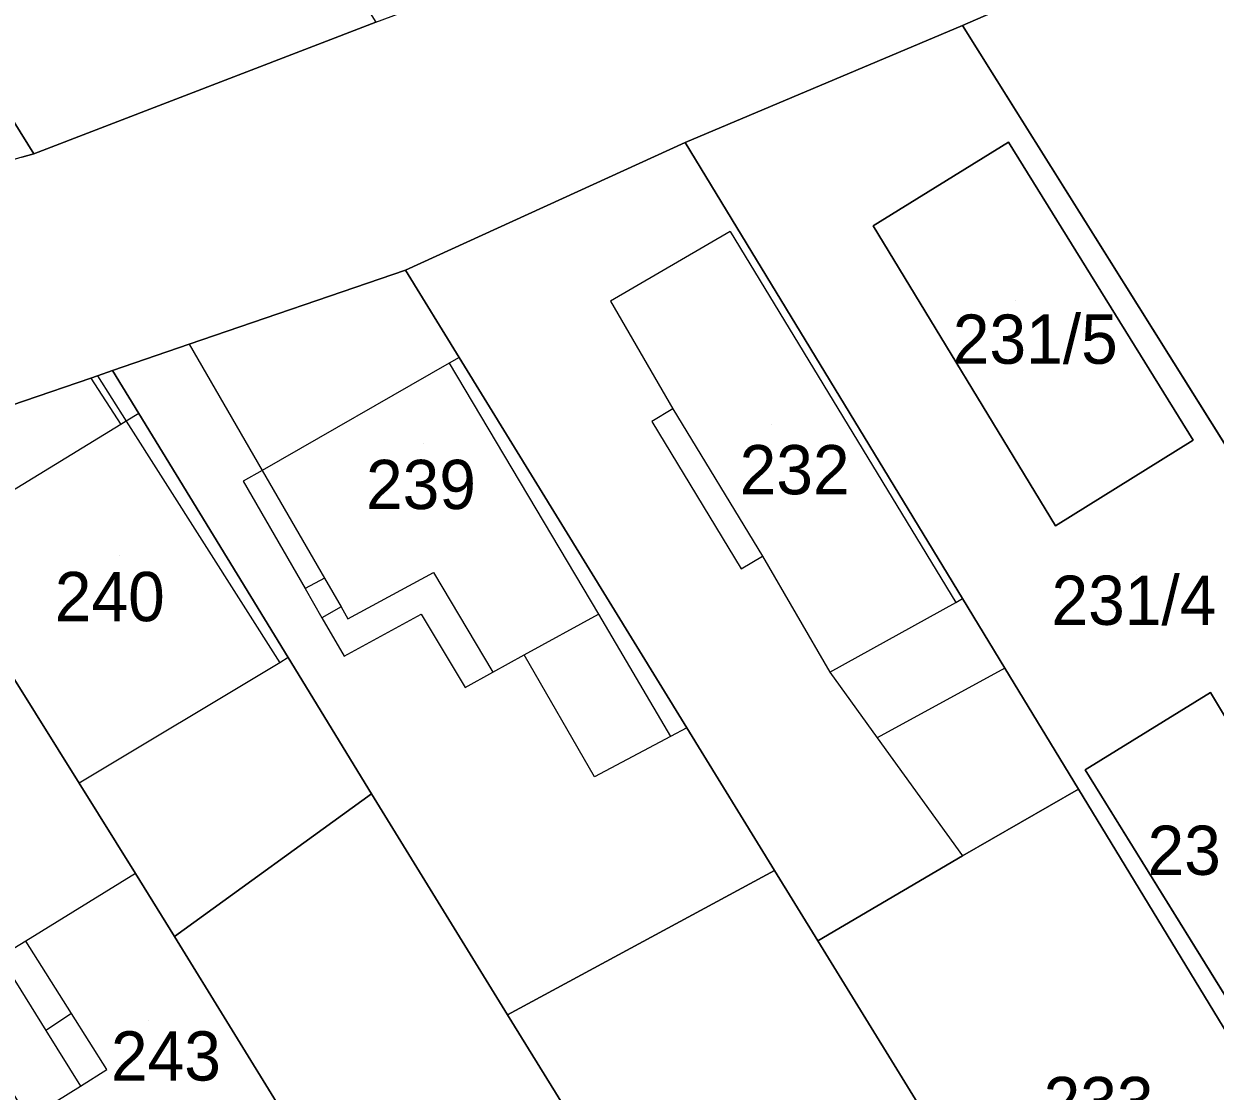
# Model space of a CAD drawing. Extents: x -263943 to -261149, y -1236934 to -1230686.
# Drawn here: x -262444.57 to -262396.23, y -1235556.72 to -1235513.39 of the extents above; entities that cross this region are included whole.
import ezdxf

# ---------------------------------------------------------------- set-up
doc = ezdxf.new("R2010")
doc.units = 0
for name, color, linetype in [('body_kn', 7, 'Continuous'), ('kladpar_druhypozemkov', 7, 'Continuous'), ('kladpar_hranice', 7, 'Continuous'), ('kladpar_parcelnecisla', 7, 'Continuous'), ('kladpar_plochy', 7, 'Continuous'), ('zappar_hrandruhpozemk', 7, 'Continuous')]:
    doc.layers.add(name, color=color, linetype=linetype)

msp = doc.modelspace()

# ---------------------------------------------------------------- linework, layer by layer
at = {"layer": 'body_kn'}
for p, q in [((-262406.48, -1235513.46), (-262406.48, -1235513.46)), ((-262417.74, -1235518.21), (-262417.74, -1235518.21)), ((-262404.61, -1235518.2), (-262404.61, -1235518.2)), ((-262404.61, -1235518.2), (-262404.61, -1235518.2)), ((-262444.17, -1235518.67), (-262444.17, -1235518.67)), ((-262415.91, -1235521.82), (-262415.91, -1235521.82)), ((-262415.64, -1235521.66), (-262415.64, -1235521.66)), ((-262410.11, -1235521.59), (-262410.11, -1235521.59)), ((-262429.08, -1235523.39), (-262429.08, -1235523.39)), ((-262420.77, -1235524.65), (-262420.77, -1235524.65)), ((-262437.86, -1235526.4), (-262437.86, -1235526.4)), ((-262437.86, -1235526.4), (-262437.86, -1235526.4)), ((-262427.31, -1235527.16), (-262427.31, -1235527.16)), ((-262426.91, -1235526.93), (-262426.91, -1235526.93)), ((-262426.91, -1235526.93), (-262426.91, -1235526.93)), ((-262441.86, -1235527.77), (-262441.86, -1235527.77)), ((-262441.86, -1235527.77), (-262441.86, -1235527.77)), ((-262441.59, -1235527.68), (-262441.59, -1235527.68)), ((-262441.59, -1235527.68), (-262441.59, -1235527.68)), ((-262440.98, -1235527.47), (-262440.98, -1235527.47)), ((-262439.91, -1235529.21), (-262439.91, -1235529.21)), ((-262439.91, -1235529.21), (-262439.91, -1235529.21)), ((-262418.23, -1235529.02), (-262418.23, -1235529.02)), ((-262418.23, -1235529.02), (-262418.23, -1235529.02)), ((-262440.64, -1235529.65), (-262440.64, -1235529.65)), ((-262440.42, -1235529.52), (-262440.42, -1235529.52)), ((-262419.09, -1235529.54), (-262419.09, -1235529.54)), ((-262397.12, -1235530.29), (-262397.12, -1235530.29)), ((-262434.9, -1235531.52), (-262434.9, -1235531.52)), ((-262435.67, -1235531.96), (-262435.67, -1235531.96)), ((-262402.71, -1235533.77), (-262402.71, -1235533.77)), ((-262414.6, -1235535), (-262414.6, -1235535)), ((-262415.46, -1235535.52), (-262415.46, -1235535.52)), ((-262432.37, -1235535.9), (-262432.37, -1235535.9)), ((-262432.37, -1235535.9), (-262432.37, -1235535.9)), ((-262427.95, -1235535.67), (-262427.95, -1235535.67)), ((-262433.16, -1235536.32), (-262433.16, -1235536.32)), ((-262406.75, -1235536.88), (-262406.75, -1235536.88)), ((-262406.75, -1235536.88), (-262406.75, -1235536.88)), ((-262406.48, -1235536.72), (-262406.48, -1235536.72)), ((-262431.7, -1235537.06), (-262431.7, -1235537.06)), ((-262428.45, -1235537.36), (-262428.45, -1235537.36)), ((-262421.25, -1235537.35), (-262421.25, -1235537.35)), ((-262432.48, -1235537.5), (-262432.48, -1235537.5)), ((-262431.42, -1235537.54), (-262431.42, -1235537.54)), ((-262434.19, -1235539.33), (-262434.19, -1235539.33)), ((-262434.19, -1235539.33), (-262434.19, -1235539.33)), ((-262433.85, -1235539.12), (-262433.85, -1235539.12)), ((-262433.85, -1235539.12), (-262433.85, -1235539.12)), ((-262431.58, -1235539.06), (-262431.58, -1235539.06)), ((-262424.27, -1235539.01), (-262424.27, -1235539.01)), ((-262424.27, -1235539.01), (-262424.27, -1235539.01)), ((-262425.54, -1235539.71), (-262425.54, -1235539.71)), ((-262411.86, -1235539.71), (-262411.86, -1235539.71)), ((-262404.76, -1235539.55), (-262404.76, -1235539.55)), ((-262404.76, -1235539.55), (-262404.76, -1235539.55)), ((-262426.67, -1235540.33), (-262426.67, -1235540.33)), ((-262396.42, -1235540.54), (-262396.42, -1235540.54)), ((-262396.42, -1235540.54), (-262396.42, -1235540.54)), ((-262417.67, -1235541.97), (-262417.67, -1235541.97)), ((-262417.67, -1235541.97), (-262417.67, -1235541.97)), ((-262418.33, -1235542.32), (-262418.33, -1235542.32)), ((-262409.94, -1235542.37), (-262409.94, -1235542.37)), ((-262401.5, -1235543.68), (-262401.5, -1235543.68)), ((-262401.5, -1235543.68), (-262401.5, -1235543.68)), ((-262442.33, -1235544.22), (-262442.33, -1235544.22)), ((-262421.41, -1235543.96), (-262421.41, -1235543.96)), ((-262430.47, -1235544.65), (-262430.47, -1235544.65)), ((-262430.47, -1235544.65), (-262430.47, -1235544.65)), ((-262401.77, -1235544.46), (-262401.77, -1235544.46)), ((-262401.77, -1235544.46), (-262401.77, -1235544.46)), ((-262406.48, -1235547.17), (-262406.48, -1235547.17)), ((-262440.04, -1235547.88), (-262440.04, -1235547.88)), ((-262440.04, -1235547.88), (-262440.04, -1235547.88)), ((-262414.11, -1235547.76), (-262414.11, -1235547.76)), ((-262438.46, -1235550.44), (-262438.46, -1235550.44)), ((-262444.5, -1235550.63), (-262444.5, -1235550.63)), ((-262444.5, -1235550.63), (-262444.5, -1235550.63)), ((-262412.35, -1235550.62), (-262412.35, -1235550.62)), ((-262442.64, -1235553.57), (-262442.64, -1235553.57)), ((-262424.94, -1235553.62), (-262424.94, -1235553.62)), ((-262424.94, -1235553.62), (-262424.94, -1235553.62)), ((-262443.68, -1235554.25), (-262443.68, -1235554.25)), ((-262441.2, -1235555.84), (-262441.2, -1235555.84)), ((-262442.27, -1235556.51), (-262442.27, -1235556.51))]:
    msp.add_line(p, q, dxfattribs=at)
at = {"layer": 'kladpar_druhypozemkov'}
for p, q in [((-262404.35, -1235524.64), (-262404.35, -1235524.64)), ((-262414.25, -1235529.64), (-262414.25, -1235529.64)), ((-262428.35, -1235530.44), (-262428.35, -1235530.44)), ((-262440.7, -1235534.99), (-262440.7, -1235534.99)), ((-262399.4, -1235535.74), (-262399.4, -1235535.74)), ((-262439.5, -1235553.84), (-262439.5, -1235553.84)), ((-262401.25, -1235556.04), (-262401.25, -1235556.04))]:
    msp.add_line(p, q, dxfattribs=at)
at = {"layer": 'kladpar_hranice'}
msp.add_line((-262396.42, -1235540.54), (-262401.5, -1235543.68), dxfattribs=at)
for points in [[(-262462.76, -1235488.73), (-262466.03, -1235483.85), (-262462.31, -1235481.58), (-262465.71, -1235475.96), (-262469.51, -1235478.23), (-262474.18, -1235470.34), (-262497.22, -1235433.33), (-262503.23, -1235423.24), (-262504.55, -1235421.03), (-262504.18, -1235420.81), (-262495.83, -1235415.83), (-262492.83, -1235420.04), (-262489.45, -1235425.16), (-262475.39, -1235445.94), (-262473.48, -1235444.88), (-262430.29, -1235513.32), (-262444.17, -1235518.67), (-262462.76, -1235488.73)], [(-262451.3, -1235520.8), (-262455.26, -1235521.99), (-262458.39, -1235516.94), (-262464.13, -1235507.7), (-262466.56, -1235503.77), (-262481.31, -1235480), (-262483.69, -1235476.16), (-262483.32, -1235475.94), (-262475.61, -1235471.22), (-262474.18, -1235470.34), (-262469.51, -1235478.23), (-262466.03, -1235483.85), (-262462.76, -1235488.73), (-262444.17, -1235518.67), (-262444.65, -1235518.81), (-262450.59, -1235520.59), (-262451.3, -1235520.8)], [(-262444.65, -1235518.81), (-262444.17, -1235518.67), (-262430.29, -1235513.32), (-262423.68, -1235510.86), (-262421.22, -1235509.96), (-262420.29, -1235509.62), (-262414, -1235507.3), (-262408.2, -1235505.17), (-262402.61, -1235503.12), (-262384.68, -1235495.02)], [(-262395.05, -1235510.73), (-262402, -1235511.5), (-262406.48, -1235513.46), (-262417.74, -1235518.21), (-262429.08, -1235523.39), (-262437.86, -1235526.4), (-262440.98, -1235527.47), (-262441.59, -1235527.68), (-262441.86, -1235527.77), (-262449.95, -1235530.54)], [(-262384.97, -1235547.8), (-262406.48, -1235513.46), (-262402, -1235511.5), (-262395.05, -1235510.73), (-262378.05, -1235537.97), (-262363.48, -1235561.29), (-262363.25, -1235561.66), (-262372.64, -1235567.43), (-262384.97, -1235547.8)], [(-262401.5, -1235543.68), (-262395.09, -1235554.03), (-262395.72, -1235554.42), (-262401.77, -1235544.46), (-262404.76, -1235539.55), (-262406.48, -1235536.72), (-262415.64, -1235521.66), (-262417.74, -1235518.21), (-262406.48, -1235513.46), (-262384.97, -1235547.8), (-262390.14, -1235550.98), (-262396.42, -1235540.54)], [(-262401.77, -1235544.46), (-262406.48, -1235547.17), (-262412.35, -1235550.62), (-262414.11, -1235547.76), (-262417.67, -1235541.97), (-262426.91, -1235526.93), (-262429.08, -1235523.39), (-262417.74, -1235518.21), (-262415.64, -1235521.66), (-262406.48, -1235536.72), (-262404.76, -1235539.55), (-262401.77, -1235544.46)], [(-262402.71, -1235533.77), (-262397.12, -1235530.29), (-262404.61, -1235518.2), (-262410.11, -1235521.59), (-262402.71, -1235533.77)], [(-262404.61, -1235518.2), (-262397.12, -1235530.29), (-262402.71, -1235533.77), (-262410.11, -1235521.59), (-262404.61, -1235518.2)], [(-262430.47, -1235544.65), (-262433.85, -1235539.12), (-262439.91, -1235529.21), (-262440.98, -1235527.47), (-262437.86, -1235526.4), (-262429.08, -1235523.39), (-262426.91, -1235526.93), (-262417.67, -1235541.97), (-262414.11, -1235547.76), (-262424.94, -1235553.62), (-262430.47, -1235544.65)], [(-262440.04, -1235547.88), (-262442.33, -1235544.22), (-262448.45, -1235534.43), (-262450.38, -1235530.69), (-262449.95, -1235530.54), (-262441.86, -1235527.77), (-262441.59, -1235527.68), (-262440.98, -1235527.47), (-262439.91, -1235529.21), (-262433.85, -1235539.12), (-262430.47, -1235544.65), (-262438.46, -1235550.44), (-262440.04, -1235547.88)], [(-262441.61, -1235562.36), (-262444.38, -1235557.83), (-262448.9, -1235550.42), (-262452.44, -1235544.63), (-262458.31, -1235535.02), (-262459.13, -1235533.68), (-262450.38, -1235530.69), (-262448.45, -1235534.43), (-262442.33, -1235544.22), (-262440.04, -1235547.88), (-262438.46, -1235550.44), (-262434, -1235557.69), (-262441.61, -1235562.36)], [(-262396.42, -1235540.54), (-262390.14, -1235550.98), (-262395.09, -1235554.03), (-262401.5, -1235543.68), (-262396.42, -1235540.54)], [(-262434, -1235557.69), (-262438.46, -1235550.44), (-262430.47, -1235544.65), (-262424.94, -1235553.62), (-262407.69, -1235581.56), (-262416.07, -1235586.4), (-262434, -1235557.69)], [(-262395.72, -1235554.42), (-262386.28, -1235569.73), (-262396.68, -1235576.1), (-262412.35, -1235550.62), (-262406.48, -1235547.17), (-262401.77, -1235544.46), (-262395.72, -1235554.42)], [(-262424.94, -1235553.62), (-262414.11, -1235547.76), (-262412.35, -1235550.62), (-262396.68, -1235576.1), (-262407.34, -1235582.13), (-262407.69, -1235581.56), (-262424.94, -1235553.62)]]:
    msp.add_lwpolyline(points, dxfattribs=at)
at = {"layer": 'kladpar_plochy'}
for p, q in [((-262444.17, -1235518.67), (-262462.76, -1235488.73)), ((-262430.29, -1235513.32), (-262444.17, -1235518.67)), ((-262417.74, -1235518.21), (-262406.48, -1235513.46)), ((-262406.48, -1235513.46), (-262384.97, -1235547.8)), ((-262415.64, -1235521.66), (-262417.74, -1235518.21)), ((-262404.61, -1235518.2), (-262410.11, -1235521.59)), ((-262397.12, -1235530.29), (-262404.61, -1235518.2)), ((-262406.48, -1235536.72), (-262415.64, -1235521.66)), ((-262410.11, -1235521.59), (-262402.71, -1235533.77)), ((-262402.71, -1235533.77), (-262397.12, -1235530.29)), ((-262404.76, -1235539.55), (-262406.48, -1235536.72)), ((-262401.77, -1235544.46), (-262404.76, -1235539.55)), ((-262396.42, -1235540.54), (-262401.5, -1235543.68)), ((-262390.14, -1235550.98), (-262396.42, -1235540.54)), ((-262401.5, -1235543.68), (-262395.09, -1235554.03)), ((-262395.72, -1235554.42), (-262401.77, -1235544.46))]:
    msp.add_line(p, q, dxfattribs=at)
for points in [[(-262451.3, -1235520.8), (-262455.26, -1235521.99), (-262458.39, -1235516.94), (-262464.13, -1235507.7), (-262466.56, -1235503.77), (-262481.31, -1235480), (-262483.69, -1235476.16), (-262483.32, -1235475.94), (-262475.61, -1235471.22), (-262474.18, -1235470.34), (-262469.51, -1235478.23), (-262466.03, -1235483.85), (-262462.76, -1235488.73), (-262444.17, -1235518.67), (-262444.65, -1235518.81), (-262450.59, -1235520.59)], [(-262384.97, -1235547.8), (-262406.48, -1235513.46), (-262402, -1235511.5), (-262395.05, -1235510.73), (-262378.05, -1235537.97), (-262363.48, -1235561.29), (-262363.25, -1235561.66), (-262372.64, -1235567.43)], [(-262401.77, -1235544.46), (-262406.48, -1235547.17), (-262412.35, -1235550.62), (-262414.11, -1235547.76), (-262417.67, -1235541.97), (-262426.91, -1235526.93), (-262429.08, -1235523.39), (-262417.74, -1235518.21), (-262415.64, -1235521.66), (-262406.48, -1235536.72), (-262404.76, -1235539.55)], [(-262404.61, -1235518.2), (-262397.12, -1235530.29), (-262402.71, -1235533.77), (-262410.11, -1235521.59)], [(-262430.47, -1235544.65), (-262433.85, -1235539.12), (-262439.91, -1235529.21), (-262440.98, -1235527.47), (-262437.86, -1235526.4), (-262429.08, -1235523.39), (-262426.91, -1235526.93), (-262417.67, -1235541.97), (-262414.11, -1235547.76), (-262424.94, -1235553.62)], [(-262440.04, -1235547.88), (-262442.33, -1235544.22), (-262448.45, -1235534.43), (-262450.38, -1235530.69), (-262449.95, -1235530.54), (-262441.86, -1235527.77), (-262441.59, -1235527.68), (-262440.98, -1235527.47), (-262439.91, -1235529.21), (-262433.85, -1235539.12), (-262430.47, -1235544.65), (-262438.46, -1235550.44)], [(-262441.61, -1235562.36), (-262444.38, -1235557.83), (-262448.9, -1235550.42), (-262452.44, -1235544.63), (-262458.31, -1235535.02), (-262459.13, -1235533.68), (-262450.38, -1235530.69), (-262448.45, -1235534.43), (-262442.33, -1235544.22), (-262440.04, -1235547.88), (-262438.46, -1235550.44), (-262434, -1235557.69)], [(-262396.42, -1235540.54), (-262390.14, -1235550.98), (-262395.09, -1235554.03), (-262401.5, -1235543.68)], [(-262434, -1235557.69), (-262438.46, -1235550.44), (-262430.47, -1235544.65), (-262424.94, -1235553.62), (-262407.69, -1235581.56), (-262416.07, -1235586.4)], [(-262395.72, -1235554.42), (-262386.28, -1235569.73), (-262396.68, -1235576.1), (-262412.35, -1235550.62), (-262406.48, -1235547.17), (-262401.77, -1235544.46)], [(-262424.94, -1235553.62), (-262414.11, -1235547.76), (-262412.35, -1235550.62), (-262396.68, -1235576.1), (-262407.34, -1235582.13), (-262407.69, -1235581.56)]]:
    msp.add_lwpolyline(points, close=True, dxfattribs=at)
for points in [[(-262444.65, -1235518.81), (-262444.17, -1235518.67), (-262430.29, -1235513.32), (-262423.68, -1235510.86), (-262421.22, -1235509.96), (-262420.29, -1235509.62), (-262414, -1235507.3), (-262408.2, -1235505.17), (-262402.61, -1235503.12), (-262384.68, -1235495.02)], [(-262395.05, -1235510.73), (-262402, -1235511.5), (-262406.48, -1235513.46), (-262417.74, -1235518.21), (-262429.08, -1235523.39), (-262437.86, -1235526.4), (-262440.98, -1235527.47), (-262441.59, -1235527.68), (-262441.86, -1235527.77), (-262449.95, -1235530.54)]]:
    msp.add_lwpolyline(points, dxfattribs=at)
at = {"layer": 'zappar_hrandruhpozemk'}
for p, q in [((-262415.91, -1235521.82), (-262406.75, -1235536.88)), ((-262437.86, -1235526.4), (-262434.9, -1235531.52)), ((-262427.31, -1235527.16), (-262434.9, -1235531.52)), ((-262426.91, -1235526.93), (-262427.31, -1235527.16)), ((-262441.86, -1235527.77), (-262440.64, -1235529.65)), ((-262418.23, -1235529.02), (-262414.6, -1235535)), ((-262419.09, -1235529.54), (-262415.46, -1235535.52)), ((-262432.37, -1235535.9), (-262433.16, -1235536.32)), ((-262411.86, -1235539.71), (-262406.75, -1235536.88)), ((-262406.75, -1235536.88), (-262406.48, -1235536.72)), ((-262431.7, -1235537.06), (-262432.48, -1235537.5)), ((-262424.27, -1235539.01), (-262421.25, -1235537.35)), ((-262434.19, -1235539.33), (-262442.33, -1235544.22)), ((-262433.85, -1235539.12), (-262434.19, -1235539.33)), ((-262421.41, -1235543.96), (-262424.27, -1235539.01)), ((-262404.76, -1235539.55), (-262409.94, -1235542.37)), ((-262440.04, -1235547.88), (-262444.5, -1235550.63)), ((-262442.64, -1235553.57), (-262444.5, -1235550.63)), ((-262442.64, -1235553.57), (-262443.68, -1235554.25)), ((-262441.2, -1235555.84), (-262442.64, -1235553.57))]:
    msp.add_line(p, q, dxfattribs=at)
for points in [[(-262415.91, -1235521.82), (-262420.77, -1235524.65), (-262418.23, -1235529.02), (-262419.09, -1235529.54)], [(-262427.31, -1235527.16), (-262421.25, -1235537.35), (-262418.33, -1235542.32)], [(-262441.59, -1235527.68), (-262440.42, -1235529.52), (-262434.19, -1235539.33)], [(-262439.91, -1235529.21), (-262440.42, -1235529.52), (-262440.64, -1235529.65), (-262448.19, -1235534.27), (-262448.45, -1235534.43)], [(-262434.9, -1235531.52), (-262435.67, -1235531.96), (-262433.16, -1235536.32), (-262432.48, -1235537.5), (-262431.58, -1235539.06), (-262428.45, -1235537.36), (-262426.67, -1235540.33), (-262425.54, -1235539.71), (-262424.27, -1235539.01)], [(-262434.9, -1235531.52), (-262432.37, -1235535.9), (-262431.7, -1235537.06)], [(-262415.46, -1235535.52), (-262414.6, -1235535), (-262411.86, -1235539.71)], [(-262431.7, -1235537.06), (-262431.42, -1235537.54), (-262427.95, -1235535.67), (-262425.54, -1235539.71)], [(-262411.86, -1235539.71), (-262409.94, -1235542.37), (-262406.48, -1235547.17)], [(-262417.67, -1235541.97), (-262418.33, -1235542.32), (-262421.41, -1235543.96)], [(-262444.5, -1235550.63), (-262445.53, -1235551.27), (-262443.68, -1235554.25), (-262442.27, -1235556.51)], [(-262444.38, -1235557.83), (-262442.27, -1235556.51), (-262441.2, -1235555.84)]]:
    msp.add_lwpolyline(points, dxfattribs=at)

# ---------------------------------------------------------------- texts
at = {"layer": 'kladpar_parcelnecisla'}
for s, p in [('231/5', (-262406.874, -1235527.19)), ('232', (-262415.525, -1235532.49)), ('239', (-262430.688, -1235533.09)), ('240', (-262443.317, -1235537.64)), ('231/4', (-262402.869, -1235537.79)), ('231/3', (-262398.971, -1235547.94)), ('243', (-262441.038, -1235556.29)), ('233', (-262403.19, -1235558.14))]:
    msp.add_text(s, height=2, dxfattribs=at).set_placement(p)

doc.saveas('drawing.dxf')
